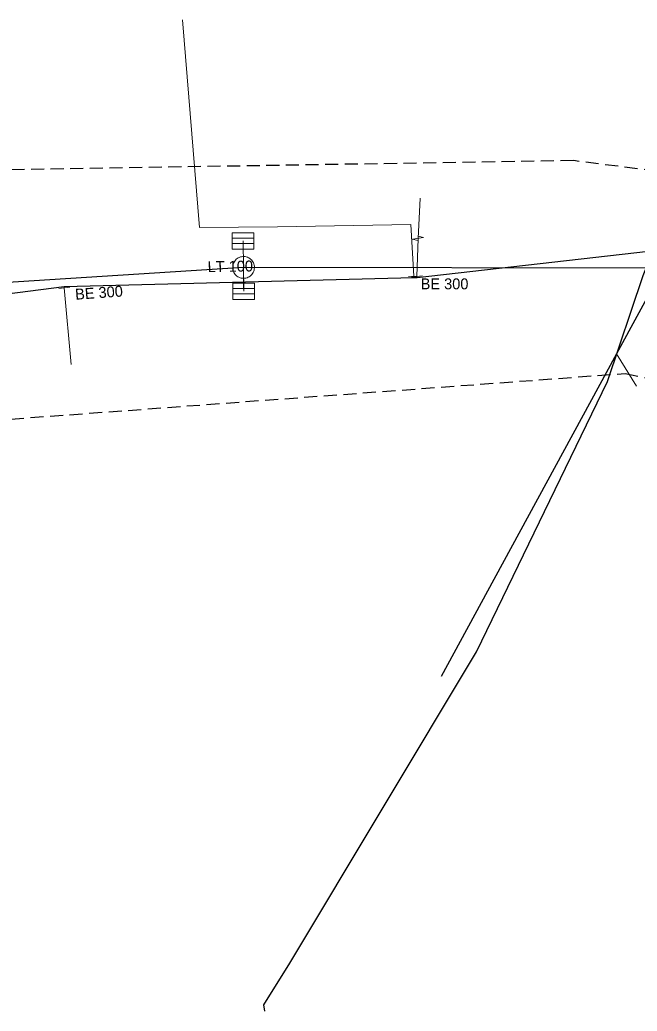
# Model space of a CAD drawing. Extents: x -687387 to -687009, y -972789 to -972578.
# Drawn here: x -687198.1 to -687141.5, y -972744.5 to -972653.5 of the extents above; entities that cross this region are included whole.
import ezdxf

# ---------------------------------------------------------------- set-up
doc = ezdxf.new("R2010")
doc.units = 0
doc.header["$LTSCALE"] = 0.4
doc.linetypes.add('MEDIUM_DASHED', pattern=[4.5, 3, -1.5])
doc.layers.add('1', color=7, linetype='Continuous')
for name, color, linetype, lineweight in [('11', 7, 'Continuous', 13), ('13', 7, 'Continuous', 13), ('14', 7, 'Continuous', 25), ('17', 7, 'Continuous', 25), ('22', 7, 'Continuous', 13), ('34', 7, 'Continuous', 13), ('47', 7, 'Continuous', 13), ('63', 7, 'MEDIUM_DASHED', 25)]:
    doc.layers.add(name, color=color, linetype=linetype, lineweight=lineweight)

msp = doc.modelspace()

# ---------------------------------------------------------------- linework, layer by layer
at = {"layer": '11'}
for p, q in [((-687177.631, -972673.771), (-687177.589, -972676.2)), ((-687177.565, -972678.395), (-687177.589, -972676.2)), ((-687141.524, -972687.105), (-687143.356, -972684.136))]:
    msp.add_line(p, q, dxfattribs=at)
at = {"layer": '13'}
msp.add_line((-687194.043, -972678.08), (-687193.413, -972685.131), dxfattribs=at)
for points in [[(-687161.96, -972677.019), (-687162.239, -972672.27), (-687174.46, -972672.469), (-687181.62, -972672.539), (-687183.199, -972653.469)], [(-687161.669, -972677.032), (-687161.57, -972673.539), (-687161.37, -972669.859)]]:
    msp.add_lwpolyline(points, dxfattribs=at)
at = {"layer": '14'}
for p, q in [((-687177.589, -972676.2), (-687202.707, -972677.802)), ((-687139.074, -972676.263), (-687177.589, -972676.2))]:
    msp.add_line(p, q, dxfattribs=at)
at = {"layer": '14', "lineweight": 13}
for p, q in [((-687161.956, -972677.145), (-687161.96, -972677.019)), ((-687161.655, -972677.153), (-687161.669, -972677.032)), ((-687194.054, -972677.975), (-687194.043, -972678.08))]:
    msp.add_line(p, q, dxfattribs=at)
at = {"layer": '14'}
msp.add_lwpolyline([(-687139.074, -972676.263), (-687143.356, -972684.136), (-687154.625, -972704.857), (-687159.462, -972713.752)], dxfattribs=at)
at = {"layer": '17'}
for points in [[(-687175.65, -972744.492), (-687175.739, -972743.912), (-687173.329, -972740.07), (-687156.205, -972711.508), (-687144.176, -972686.673), (-687140.919, -972676.959), (-687140.013, -972674.707), (-687139.168, -972673.949)], [(-687140.419, -972674.734), (-687161.655, -972677.153), (-687161.956, -972677.145), (-687194.054, -972677.975), (-687218.609, -972681.129), (-687239.739, -972685.945)]]:
    msp.add_lwpolyline(points, dxfattribs=at)
at = {"layer": '22'}
for p, q in [((-687178.642, -972673.514), (-687176.642, -972673.514)), ((-687178.642, -972674.014), (-687176.642, -972674.014)), ((-687177.589, -972678.2), (-687177.588, -972675.2)), ((-687178.576, -972678.138), (-687176.576, -972678.138)), ((-687178.576, -972678.638), (-687176.576, -972678.638))]:
    msp.add_line(p, q, dxfattribs=at)
for points in [[(-687178.642, -972673.014), (-687176.642, -972673.014), (-687176.642, -972674.514), (-687178.642, -972674.514)], [(-687176.589, -972676.2), (-687176.594, -972676.091), (-687176.612, -972675.983), (-687176.642, -972675.877), (-687176.682, -972675.776), (-687176.734, -972675.679), (-687176.796, -972675.589), (-687176.868, -972675.506), (-687176.948, -972675.432), (-687177.036, -972675.366), (-687177.13, -972675.311), (-687177.23, -972675.266), (-687177.335, -972675.233), (-687177.442, -972675.211), (-687177.551, -972675.201), (-687177.661, -972675.203), (-687177.769, -972675.217), (-687177.876, -972675.242), (-687177.979, -972675.279), (-687178.077, -972675.328), (-687178.169, -972675.386), (-687178.255, -972675.455), (-687178.332, -972675.532), (-687178.401, -972675.618), (-687178.46, -972675.71), (-687178.508, -972675.808), (-687178.545, -972675.911), (-687178.571, -972676.018), (-687178.585, -972676.126), (-687178.588, -972676.236), (-687178.578, -972676.345), (-687178.557, -972676.452), (-687178.523, -972676.556), (-687178.479, -972676.656), (-687178.424, -972676.751), (-687178.358, -972676.839), (-687178.284, -972676.919), (-687178.201, -972676.991), (-687178.111, -972677.053), (-687178.015, -972677.105), (-687177.913, -972677.146), (-687177.808, -972677.176), (-687177.7, -972677.194), (-687177.59, -972677.2), (-687177.481, -972677.194), (-687177.373, -972677.176), (-687177.268, -972677.147), (-687177.166, -972677.106), (-687177.069, -972677.054), (-687176.979, -972676.992), (-687176.896, -972676.921), (-687176.821, -972676.841), (-687176.756, -972676.753), (-687176.7, -972676.659), (-687176.656, -972676.559), (-687176.622, -972676.455), (-687176.6, -972676.347), (-687176.59, -972676.238)], [(-687178.576, -972677.638), (-687176.576, -972677.638), (-687176.576, -972679.138), (-687178.576, -972679.138)]]:
    msp.add_lwpolyline(points, close=True, dxfattribs=at)
at = {"layer": '34'}
for p, q in [((-687162.459, -972677.032), (-687161.46, -972677.006)), ((-687162.165, -972677.089), (-687161.172, -972676.975)), ((-687193.545, -972678.027), (-687194.54, -972678.131))]:
    msp.add_line(p, q, dxfattribs=at)
at = {"layer": '47'}
msp.add_line((-687162.074, -972673.609), (-687161.58, -972673.739), dxfattribs=at)
msp.add_lwpolyline([(-687162.074, -972673.609), (-687161.065, -972673.468), (-687161.559, -972673.338)], dxfattribs=at)
at = {"layer": '63'}
msp.add_lwpolyline([(-687198.94, -972690.124), (-687142.558, -972685.938), (-687142.558, -972685.938), (-687071.103, -972701.568), (-687071.103, -972701.568), (-687078.081, -972717.199), (-687078.081, -972717.199), (-687052.96, -972718.874), (-687052.96, -972718.874), (-687039.004, -972700.731), (-687039.004, -972700.731), (-687036.212, -972687.333), (-687036.212, -972687.333), (-687054.635, -972678.68), (-687054.635, -972678.68), (-687058.542, -972684.542), (-687058.542, -972684.542), (-687096.782, -972672.819), (-687096.782, -972672.819), (-687147.303, -972666.399), (-687147.303, -972666.399), (-687234.11, -972667.795)], dxfattribs=at)

# ---------------------------------------------------------------- texts
at = {"layer": '1'}
for s, rotation, p in [('LT 100', 1, (-687180.878, -972676.639)), ('BE 300', 4, (-687193.016, -972679.173))]:
    msp.add_text(s, height=1, rotation=rotation, dxfattribs=at).set_placement(p)
msp.add_text('BE 300', height=1, dxfattribs=at).set_placement((-687161.334, -972678.212))

doc.saveas('drawing.dxf')
